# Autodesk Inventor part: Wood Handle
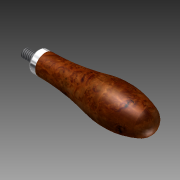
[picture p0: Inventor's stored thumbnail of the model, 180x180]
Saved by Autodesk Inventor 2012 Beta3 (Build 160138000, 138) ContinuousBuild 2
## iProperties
Created: 2010-12
Part Number: Wood Handle
Document SubType Name: Modeling
Designer: Thom Tremblay
Density: 1 g/cm^3
Material: Default
Author: Thom Tremblay
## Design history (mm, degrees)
sketch "Sketch1"
  geometry: L1 (93.367, -68.499)-(103.527, -68.499); L2 (103.527, -68.499)-(103.527, -65.324); L3 (103.527, -65.324)-(93.367, -65.324); L4 (93.367, -65.324)-(93.367, -68.499); L5 (103.527, -68.499)-(108.607, -68.499); L6 (108.607, -68.499)-(108.607, -60.879); L7 (108.607, -60.879)-(103.527, -60.879); L8 (103.527, -60.879)-(103.527, -68.499); L9 (192.427, -68.499)-(108.607, -68.499); L10 (192.427, -68.499)-(192.427, -75.403); A1 r 177.8 centre (108.607, 116.921) between (108.607, -60.879) and (149.179, -56.188); A2 r 60.96 centre (163.089, -115.54) between (186.103, -59.091) and (149.179, -56.188); A3 r 10.16 centre (182.267, -68.499) between (192.427, -68.499) and (186.103, -59.091); 1 further point
  constraints: 20 end point, 6 point on circle, 4 parallel, 4 tangent, 3 centre point, 3 perpendicular, 2 horizontal, 1 collinear
  dimensions: "d0" = 10.16 distance of L3.end L2.end; "d1" = 3.175 distance of L2.end L1.end; "d2" = 5.08 distance of L7.end L6.end; "d3" = 7.62 distance of L6.end L5.end; "d4" = 88.9 distance between parallel lines of L10 L2; "d5" = 60.96 radius of A2; "d6" = 177.8 radius of A1; "d7" = 10.16 radius of A3
revolve "Revolution1" sketch "Sketch1" stored, may be unused: angle "d8" = 90 deg
thread "Thread1" dims "d9" = 8.89, "d10" = 0
fillet "Fillet1" dims "d11" = 1.27
body "Solid1"
